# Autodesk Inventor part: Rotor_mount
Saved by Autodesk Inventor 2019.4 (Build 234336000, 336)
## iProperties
Created: 2020-02
Part Number: Rotor_mount
Material: Generic
Document SubType Name: Modeling
Designer: Administrator
Density: 1 g/cm^3
Appearance: Default
Title: Rotor_mount v9
Author: Administrator
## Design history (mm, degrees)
feature "Body2"
body "Solid1"
